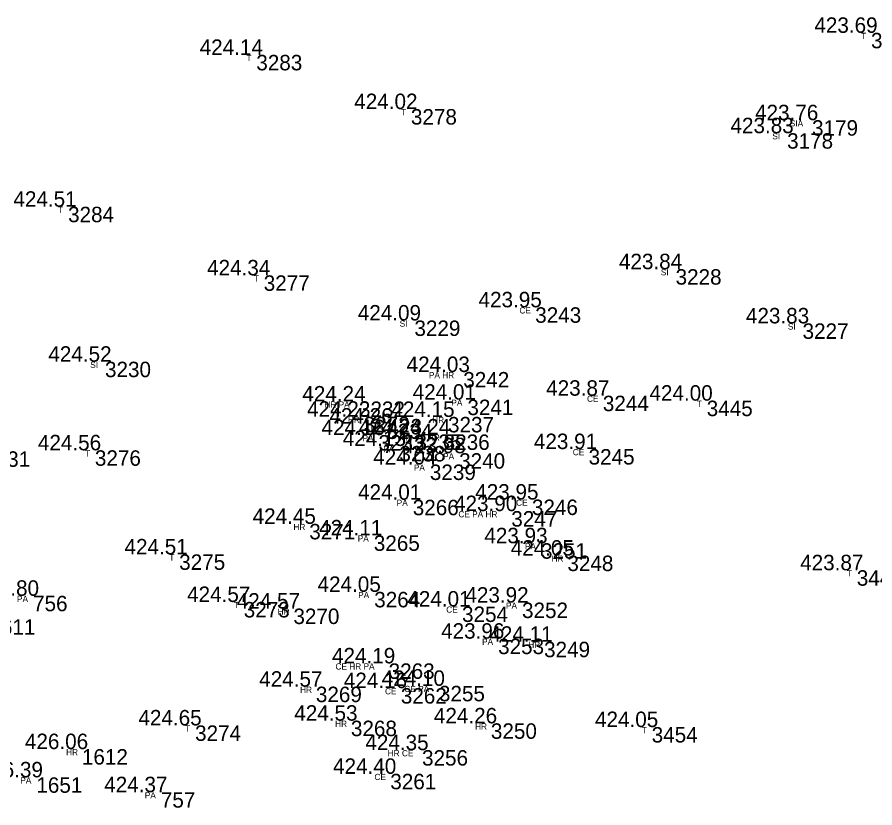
# Model space of a CAD drawing. Extents: x -639390 to -639075, y -1138747 to -1138358.
# Drawn here: x -639243.09 to -639201.49, y -1138555.66 to -1138517.29 of the extents above; entities that cross this region are included whole.
import ezdxf

# ---------------------------------------------------------------- set-up
doc = ezdxf.new("R2010")
doc.units = 0
for name, color, linetype in [('Vrstva 11', 7, 'Continuous'), ('Vrstva 12', 7, 'Continuous'), ('Vrstva 13', 7, 'Continuous'), ('Vrstva 57', 7, 'Continuous')]:
    doc.layers.add(name, color=color, linetype=linetype)

msp = doc.modelspace()

# ---------------------------------------------------------------- linework, layer by layer
at = {"layer": 'Vrstva 11'}
for p, q in [((-639201.95, -1138518.05), (-639201.95, -1138518.05)), ((-639231.77, -1138519.12), (-639231.77, -1138519.12)), ((-639224.27, -1138521.75), (-639224.27, -1138521.75)), ((-639204.81, -1138522.29), (-639204.81, -1138522.29)), ((-639206.02, -1138522.92), (-639206.02, -1138522.92)), ((-639240.9, -1138526.49), (-639240.9, -1138526.49)), ((-639231.41, -1138529.82), (-639231.41, -1138529.82)), ((-639211.43, -1138529.52), (-639211.43, -1138529.52)), ((-639218.24, -1138531.37), (-639218.24, -1138531.37)), ((-639224.1, -1138532.01), (-639224.1, -1138532.01)), ((-639205.27, -1138532.15), (-639205.27, -1138532.15)), ((-639239.11, -1138534.01), (-639239.11, -1138534.01)), ((-639221.73, -1138534.51), (-639221.73, -1138534.51)), ((-639214.96, -1138535.66), (-639214.96, -1138535.66)), ((-639226.79, -1138535.94), (-639226.79, -1138535.94)), ((-639221.53, -1138535.85), (-639221.53, -1138535.85)), ((-639209.92, -1138535.9), (-639209.92, -1138535.9)), ((-639226.56, -1138536.68), (-639226.56, -1138536.68)), ((-639222.47, -1138536.69), (-639222.47, -1138536.69)), ((-639225.46, -1138537.01), (-639225.46, -1138537.01)), ((-639225.84, -1138537.57), (-639225.84, -1138537.57)), ((-639224.05, -1138537.54), (-639224.05, -1138537.54)), ((-639222.68, -1138537.54), (-639222.68, -1138537.54)), ((-639224.83, -1138538.1), (-639224.83, -1138538.1)), ((-639239.6, -1138538.31), (-639239.6, -1138538.31)), ((-639221.93, -1138538.45), (-639221.93, -1138538.45)), ((-639215.65, -1138538.25), (-639215.65, -1138538.25)), ((-639223.35, -1138539), (-639223.35, -1138539)), ((-639224.18, -1138540.71), (-639224.18, -1138540.71)), ((-639218.4, -1138540.7), (-639218.4, -1138540.7)), ((-639219.4, -1138541.26), (-639219.4, -1138541.26)), ((-639229.2, -1138541.88), (-639229.2, -1138541.88)), ((-639226.07, -1138542.44), (-639226.07, -1138542.44)), ((-639217.96, -1138542.82), (-639217.96, -1138542.82)), ((-639235.51, -1138543.36), (-639235.51, -1138543.36)), ((-639216.68, -1138543.42), (-639216.68, -1138543.42)), ((-639202.64, -1138544.13), (-639202.64, -1138544.13)), ((-639226.05, -1138545.18), (-639226.05, -1138545.18)), ((-639242.6, -1138545.37), (-639242.6, -1138545.37)), ((-639232.38, -1138545.67), (-639232.38, -1138545.67)), ((-639229.97, -1138545.99), (-639229.97, -1138545.99)), ((-639221.79, -1138545.89), (-639221.79, -1138545.89)), ((-639218.88, -1138545.7), (-639218.88, -1138545.7)), ((-639220.04, -1138547.45), (-639220.04, -1138547.45)), ((-639217.81, -1138547.6), (-639217.81, -1138547.6)), ((-639225.35, -1138548.65), (-639225.35, -1138548.65)), ((-639228.88, -1138549.78), (-639228.88, -1138549.78)), ((-639222.91, -1138549.74), (-639222.91, -1138549.74)), ((-639224.76, -1138549.85), (-639224.76, -1138549.85)), ((-639227.18, -1138551.43), (-639227.18, -1138551.43)), ((-639234.74, -1138551.66), (-639234.74, -1138551.66)), ((-639220.39, -1138551.56), (-639220.39, -1138551.56)), ((-639212.59, -1138551.74), (-639212.59, -1138551.74)), ((-639240.23, -1138552.81), (-639240.23, -1138552.81)), ((-639223.73, -1138552.86), (-639223.73, -1138552.86)), ((-639242.44, -1138554.18), (-639242.44, -1138554.18)), ((-639225.27, -1138554.01), (-639225.27, -1138554.01)), ((-639236.4, -1138554.9), (-639236.4, -1138554.9))]:
    msp.add_line(p, q, dxfattribs=at)

# ---------------------------------------------------------------- texts
at = {"layer": 'Vrstva 12'}
for s, p in [('423.69 ', (-639204.419, -1138518.05)), ('424.14 ', (-639234.239, -1138519.12)), ('424.02 ', (-639226.739, -1138521.75)), ('423.76 ', (-639207.296, -1138522.29)), ('423.83 ', (-639208.489, -1138522.92)), ('424.51 ', (-639243.275, -1138526.49)), ('423.84 ', (-639213.899, -1138529.52)), ('424.34 ', (-639233.879, -1138529.82)), ('423.95 ', (-639220.71, -1138531.37)), ('424.09 ', (-639226.569, -1138532.01)), ('423.83 ', (-639207.739, -1138532.15)), ('424.52 ', (-639241.579, -1138534.01)), ('424.03 ', (-639224.199, -1138534.51)), ('424.24 ', (-639229.259, -1138535.94)), ('424.01 ', (-639223.905, -1138535.85)), ('423.87 ', (-639217.429, -1138535.66)), ('424.00 ', (-639212.419, -1138535.9)), ('424.22 ', (-639229.029, -1138536.68)), ('424.15 ', (-639224.94, -1138536.69)), ('424.26 ', (-639227.946, -1138537.01)), ('424.16 ', (-639228.326, -1138537.57)), ('424.23 ', (-639226.519, -1138537.54)), ('424.24 ', (-639225.149, -1138537.54)), ('424.13 ', (-639227.299, -1138538.1)), ('424.56 ', (-639242.086, -1138538.31)), ('423.98 ', (-639224.399, -1138538.45)), ('423.91 ', (-639218.025, -1138538.25)), ('424.04 ', (-639225.819, -1138539)), ('424.01 ', (-639226.555, -1138540.71)), ('423.95 ', (-639220.87, -1138540.7)), ('423.90 ', (-639221.899, -1138541.26)), ('424.45 ', (-639231.67, -1138541.88)), ('424.11 ', (-639228.445, -1138542.44)), ('423.93 ', (-639220.429, -1138542.82)), ('424.51 ', (-639237.885, -1138543.36)), ('424.05 ', (-639219.15, -1138543.42)), ('423.87 ', (-639205.109, -1138544.13)), ('424.05 ', (-639228.52, -1138545.18)), ('424.80 ', (-639245.099, -1138545.37)), ('424.57 ', (-639234.849, -1138545.67)), ('424.57 ', (-639232.439, -1138545.99)), ('424.01 ', (-639224.165, -1138545.89)), ('423.92 ', (-639221.349, -1138545.7)), ('423.96 ', (-639222.526, -1138547.45)), ('424.11 ', (-639220.185, -1138547.6)), ('424.19 ', (-639227.819, -1138548.65)), ('424.10 ', (-639225.409, -1138549.74)), ('424.57 ', (-639231.349, -1138549.78)), ('424.16 ', (-639227.246, -1138549.85)), ('424.53 ', (-639229.649, -1138551.43)), ('424.65 ', (-639237.21, -1138551.66)), ('424.26 ', (-639222.876, -1138551.56)), ('424.05 ', (-639215.06, -1138551.74)), ('426.06 ', (-639242.716, -1138552.81)), ('424.35 ', (-639226.2, -1138552.86)), ('426.39 ', (-639244.909, -1138554.18)), ('424.40 ', (-639227.769, -1138554.01)), ('424.37 ', (-639238.869, -1138554.9))]:
    msp.add_text(s, height=0.75, dxfattribs=at).set_placement(p)
at = {"layer": 'Vrstva 13'}
for s, p in [(' 3167', (-639201.95, -1138518.8)), (' 3283', (-639231.77, -1138519.87)), (' 3278', (-639224.27, -1138522.5)), (' 3179', (-639204.81, -1138523.04)), (' 3178', (-639206.02, -1138523.67)), (' 3284', (-639240.9, -1138527.24)), (' 3277', (-639231.41, -1138530.57)), (' 3228', (-639211.43, -1138530.27)), (' 3243', (-639218.24, -1138532.12)), (' 3229', (-639224.1, -1138532.76)), (' 3227', (-639205.27, -1138532.9)), (' 3230', (-639239.11, -1138534.76)), (' 3242', (-639221.73, -1138535.26)), (' 3244', (-639214.96, -1138536.41)), (' 3232', (-639226.79, -1138536.69)), (' 3241', (-639221.53, -1138536.6)), (' 3445', (-639209.92, -1138536.65)), (' 3272', (-639226.56, -1138537.43)), (' 3237', (-639222.47, -1138537.44)), (' 3234', (-639225.46, -1138537.76)), (' 3233', (-639225.84, -1138538.32)), (' 3235', (-639224.05, -1138538.29)), (' 3236', (-639222.68, -1138538.29)), (' 3238', (-639224.83, -1138538.85)), (' 3231', (-639244.97, -1138539.11)), (' 3276', (-639239.6, -1138539.06)), (' 3240', (-639221.93, -1138539.2)), (' 3245', (-639215.65, -1138539)), (' 3239', (-639223.35, -1138539.75)), (' 3246', (-639218.4, -1138541.45)), (' 3266', (-639224.18, -1138541.46)), (' 3247', (-639219.4, -1138542.01)), (' 3271', (-639229.2, -1138542.63)), (' 3265', (-639226.07, -1138543.19)), (' 3251', (-639217.96, -1138543.57)), (' 3275', (-639235.51, -1138544.11)), (' 3248', (-639216.68, -1138544.17)), (' 3446', (-639202.64, -1138544.88)), (' 3264', (-639226.05, -1138545.93)), (' 756', (-639242.6, -1138546.12)), (' 3273', (-639232.38, -1138546.42)), (' 3270', (-639229.97, -1138546.74)), (' 3254', (-639221.79, -1138546.64)), (' 3252', (-639218.88, -1138546.45)), (' 1611', (-639244.72, -1138547.26)), (' 3253', (-639220.04, -1138548.2)), (' 3249', (-639217.81, -1138548.35)), (' 3263', (-639225.35, -1138549.4)), (' 3269', (-639228.88, -1138550.53)), (' 3262', (-639224.76, -1138550.6)), (' 3255', (-639222.91, -1138550.49)), (' 3268', (-639227.18, -1138552.18)), (' 3274', (-639234.74, -1138552.41)), (' 3250', (-639220.39, -1138552.31)), (' 3454', (-639212.59, -1138552.49)), (' 1612', (-639240.23, -1138553.56)), (' 3256', (-639223.73, -1138553.61)), (' 3261', (-639225.27, -1138554.76)), (' 1651', (-639242.44, -1138554.93)), (' 757', (-639236.4, -1138555.65))]:
    msp.add_text(s, height=0.75, dxfattribs=at).set_placement(p)
at = {"layer": 'Vrstva 57'}
for s, p in [('T', (-639202.15, -1138518.35)), ('T', (-639231.97, -1138519.42)), ('T', (-639224.47, -1138522.05)), ('SIA', (-639205.61, -1138522.59)), ('SI', (-639206.458, -1138523.22)), ('T', (-639241.1, -1138526.79)), ('T', (-639231.61, -1138530.12)), ('SI', (-639211.868, -1138529.82)), ('CE', (-639218.728, -1138531.67)), ('SI', (-639224.538, -1138532.31)), ('SI', (-639205.708, -1138532.45)), ('SI', (-639239.548, -1138534.31)), ('PA HR', (-639223.119, -1138534.81)), ('CE', (-639215.448, -1138535.96)), ('HR PA', (-639228.19, -1138536.24)), ('PA', (-639222.03, -1138536.15)), ('T', (-639210.12, -1138536.2)), ('HR', (-639227.049, -1138536.98)), ('HR', (-639222.959, -1138536.99)), ('HR', (-639225.949, -1138537.31)), ('PA', (-639226.34, -1138537.87)), ('HR', (-639224.539, -1138537.84)), ('HR', (-639223.169, -1138537.84)), ('PA', (-639225.33, -1138538.4)), ('T', (-639239.8, -1138538.61)), ('PA', (-639222.43, -1138538.75)), ('CE', (-639216.138, -1138538.55)), ('PA', (-639223.85, -1138539.3)), ('PA', (-639224.68, -1138541.01)), ('CE', (-639218.888, -1138541)), ('CE PA HR', (-639221.689, -1138541.56)), ('HR', (-639229.689, -1138542.18)), ('PA', (-639226.57, -1138542.74)), ('PA', (-639218.46, -1138543.12)), ('T', (-639235.71, -1138543.66)), ('HR', (-639217.169, -1138543.72)), ('T', (-639202.84, -1138544.43)), ('PA', (-639226.55, -1138545.48)), ('PA', (-639243.1, -1138545.67)), ('T', (-639232.58, -1138545.97)), ('HR', (-639230.459, -1138546.29)), ('CE', (-639222.277, -1138546.19)), ('PA', (-639219.38, -1138546)), ('PA', (-639220.54, -1138547.75)), ('HR', (-639218.299, -1138547.9)), ('CE HR PA', (-639227.65, -1138548.95)), ('HR', (-639229.369, -1138550.08)), ('CE', (-639225.248, -1138550.15)), ('CE PA', (-639224.31, -1138550.04)), ('HR', (-639227.669, -1138551.73)), ('T', (-639234.94, -1138551.96)), ('HR', (-639220.879, -1138551.86)), ('T', (-639212.79, -1138552.04)), ('HR', (-639240.719, -1138553.11)), ('HR CE', (-639225.118, -1138553.16)), ('CE', (-639225.758, -1138554.31)), ('PA', (-639242.94, -1138554.48)), ('PA', (-639236.9, -1138555.2))]:
    msp.add_text(s, height=0.3, dxfattribs=at).set_placement(p)

doc.saveas('drawing.dxf')
